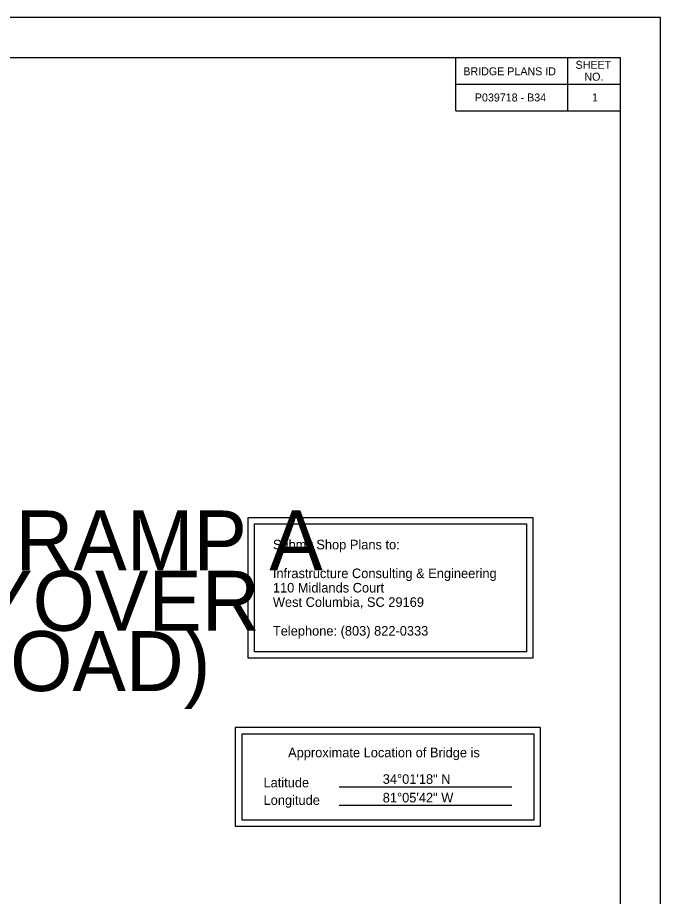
# Model space of a CAD drawing. Extents: x -1142 to 658, y -589 to 511.
# Drawn here: x 256 to 658, y -39 to 511 of the extents above; entities that cross this region are included whole.
import ezdxf

# ---------------------------------------------------------------- set-up
doc = ezdxf.new("R2010")
doc.units = 0
for name, color, linetype in [('BR_BORDER LINES', 7, 'Continuous'), ('BR_DETAILS', 7, 'Continuous'), ('BR_TEXT', 7, 'Continuous'), ('Default', 7, 'Continuous'), ('Level 31', 7, 'Continuous')]:
    doc.layers.add(name, color=color, linetype=linetype)

msp = doc.modelspace()

# ---------------------------------------------------------------- linework, layer by layer
at = {"layer": 'BR_BORDER LINES'}
for p, q in [((-1041.79, 485.67), (633.21, 485.67)), ((530.21, 452.33), (530.21, 485.67)), ((600.21, 452.33), (600.21, 485.67)), ((633.21, -564.26), (633.21, 485.67)), ((530.21, 469), (633.21, 469)), ((530.21, 452.33), (633.21, 452.33)), ((633.21, 427.4), (633.21, 452.27)), ((633.21, 75.01), (633.21, 427.47))]:
    msp.add_line(p, q, dxfattribs=at)
at = {"layer": 'Default'}
for p, q in [((457.1, 29.29), (565.24, 29.29)), ((457.1, 17.7), (565.24, 17.7))]:
    msp.add_line(p, q, dxfattribs=at)
for points in [[(400.22, 197.77), (578.44, 197.77), (578.44, 109.74), (400.22, 109.74)], [(404.22, 193.77), (574.44, 193.77), (574.44, 113.74), (404.22, 113.74)], [(583.24, 66.29), (392.18, 66.29), (392.18, 4.7), (583.24, 4.7)], [(579.24, 62.29), (396.18, 62.29), (396.18, 8.7), (579.24, 8.7)]]:
    msp.add_lwpolyline(points, close=True, dxfattribs=at)
at = {"layer": 'Level 31'}
msp.add_line((658.21, 510.67), (-1141.79, 510.67), dxfattribs=at)
msp.add_lwpolyline([(-1141.79, 510.67), (-1141.79, -589.33), (658.21, -589.33), (658.21, 510.67)], dxfattribs=at)

# ---------------------------------------------------------------- texts
at = {"layer": 'BR_DETAILS'}
for s, height, p in [('BRIDGE PLANS ID', 5.0001, (534.89, 474.55)), ('SHEET', 5, (605.1, 478.6)), ('NO.', 5, (610.64, 471.16))]:
    msp.add_text(s, height=height, dxfattribs=at).set_placement(p)
at = {"layer": 'BR_TEXT'}
for s, p in [('P039718 - B34', (542.08, 458.17)), ('1', (615.41, 458.17))]:
    msp.add_text(s, height=5, dxfattribs=at).set_placement(p)
at = {"layer": 'Default'}
for s, height, p in [('ROAD S-2963 (COLONIAL LIFE BLVD.)  RAMP A', 37.5, (-673.36, 164.69)), ('Submit Shop Plans to:', 6, (415.7, 177.87)), ('Infrastructure Consulting & Engineering', 6, (415.7, 159.87)), ('BRIDGE OVER RAMP I-126 WB TO FLYOVER', 37.5, (-654.17, 126.94)), ('110 Midlands Court', 6, (415.7, 150.87)), ('West Columbia, SC 29169', 6, (415.7, 141.87)), ('AND ROAD S-287 (ARROWWOOD ROAD)', 37.5, (-595.71, 89.19)), ('Telephone: (803) 822-0333', 6, (415.7, 123.87)), ('Approximate Location of Bridge is', 6, (425.23, 47.73)), ('Latitude', 6, (409.82, 28.92)), ('34%%D01\'18" N', 6, (484.46, 31.12)), ('Longitude', 6, (409.87, 17.96)), ('81%%D05\'42" W', 6, (484.46, 19.5))]:
    msp.add_text(s, height=height, dxfattribs=at).set_placement(p)

doc.saveas('drawing.dxf')
